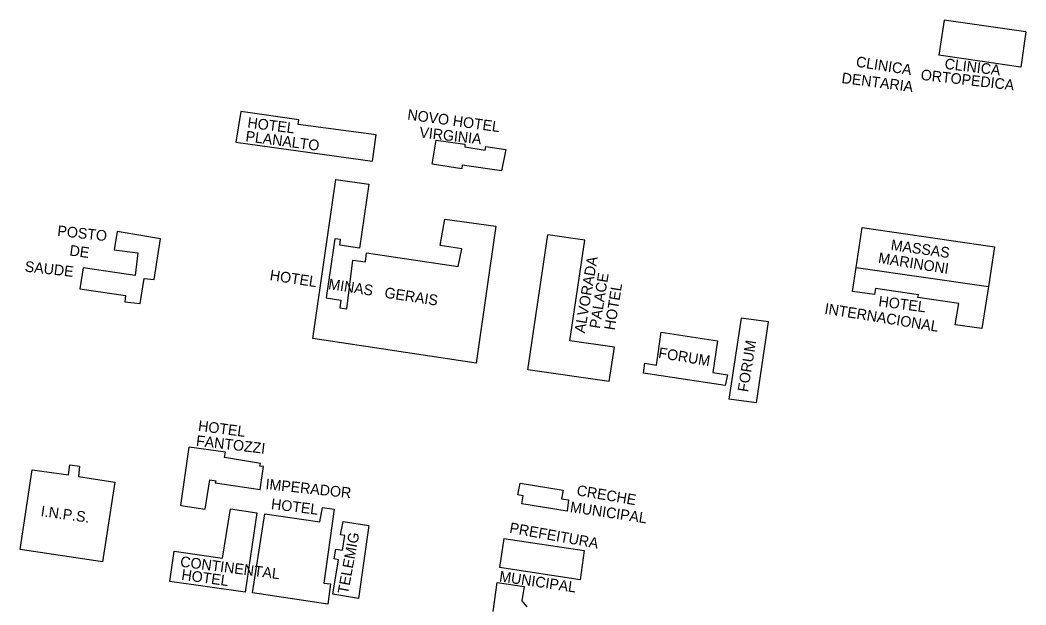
# Model space of a CAD drawing. Extents: x 325899 to 363134, y 7578590 to 7592502.
# Drawn here: x 337903.7 to 338282.4, y 7590177.9 to 7590398 of the extents above; entities that cross this region are included whole.
import ezdxf

# ---------------------------------------------------------------- set-up
doc = ezdxf.new("R2010")
doc.units = 0
doc.layers.add('EDIFEXISTENT', color=7, linetype='Continuous')
doc.layers.add('EDIFIDENTIF', color=7, linetype='Continuous')

msp = doc.modelspace()

# ---------------------------------------------------------------- linework, layer by layer
at = {"layer": 'EDIFEXISTENT'}
for p, q in [((338251.55, 7590398.05), (338249.66, 7590384.84)), ((338282.38, 7590393.63), (338251.55, 7590398.05)), ((338282.38, 7590393.63), (338280.49, 7590380.32)), ((338280.49, 7590380.32), (338249.66, 7590384.84)), ((338249.66, 7590384.84), (338249.66, 7590384.84)), ((337986.75, 7590363.66), (337984.97, 7590352.14)), ((338008.58, 7590360.47), (337986.75, 7590363.66)), ((337986.75, 7590363.66), (337986.75, 7590363.66)), ((338008.4, 7590358.72), (338008.58, 7590360.47)), ((338037.71, 7590354.92), (338008.4, 7590358.72)), ((338036.33, 7590344.99), (338037.71, 7590354.92)), ((337984.97, 7590352.14), (338036.33, 7590344.99)), ((338058.88, 7590343.78), (338060.3, 7590352.86)), ((338060.3, 7590352.86), (338071.14, 7590351.41)), ((338071.14, 7590351.41), (338071.08, 7590350.31)), ((338071.08, 7590350.31), (338078.77, 7590349.13)), ((338078.77, 7590349.13), (338079, 7590350.43)), ((338079, 7590350.43), (338086.53, 7590349.29)), ((338086.53, 7590349.29), (338084.94, 7590341.32)), ((338069.99, 7590342.1), (338058.88, 7590343.78)), ((338070.19, 7590343.4), (338069.99, 7590342.1)), ((338084.94, 7590341.32), (338070.19, 7590343.4)), ((338013.89, 7590278.15), (338022.51, 7590338.11)), ((338022.51, 7590338.11), (338035.03, 7590336.24)), ((338035.03, 7590336.24), (338031.5, 7590312.27)), ((338061.81, 7590313.17), (338063.64, 7590323.12)), ((338063.64, 7590323.12), (338082.84, 7590320.46)), ((338082.84, 7590320.46), (338075.44, 7590268.92)), ((338218.53, 7590304.91), (338220.73, 7590319.98)), ((338220.73, 7590319.98), (338270.62, 7590312.77)), ((337940.18, 7590318.51), (337939.1, 7590311.56)), ((337956.49, 7590315.75), (337940.18, 7590318.51)), ((338022.24, 7590315.78), (338018.89, 7590293.51)), ((338024.34, 7590315.52), (338022.24, 7590315.78)), ((338094.82, 7590266.47), (338102.37, 7590317.27)), ((338116.29, 7590315.21), (338102.37, 7590317.27)), ((337954.15, 7590300.36), (337956.49, 7590315.75)), ((338024.08, 7590313.31), (338024.34, 7590315.52)), ((338031.5, 7590312.27), (338024.08, 7590313.31)), ((338069.99, 7590311.92), (338061.81, 7590313.17)), ((338110.66, 7590277.31), (338116.29, 7590315.21)), ((338270.62, 7590312.77), (338268.24, 7590297.79)), ((337939.1, 7590311.56), (337947.96, 7590310.46)), ((337947.96, 7590310.46), (337947.04, 7590301.95)), ((338033.72, 7590307.1), (338034.11, 7590310.43)), ((338034.11, 7590310.43), (338068.67, 7590305.35)), ((338068.67, 7590305.35), (338069.99, 7590311.92)), ((337927.49, 7590304.78), (337926.2, 7590296.91)), ((337947.04, 7590301.95), (337927.49, 7590304.78)), ((338026.73, 7590289.32), (338028.94, 7590307.68)), ((338028.94, 7590307.68), (338033.72, 7590307.1)), ((338217.04, 7590295.9), (338218.53, 7590304.91)), ((338218.53, 7590304.91), (338268.24, 7590297.79)), ((337948.89, 7590291.33), (337950.37, 7590300.75)), ((337950.37, 7590300.75), (337954.15, 7590300.36)), ((337926.2, 7590296.91), (337943.39, 7590294.37)), ((338225.77, 7590297), (338225.38, 7590294.81)), ((338241.95, 7590294.67), (338225.77, 7590297)), ((338268.24, 7590297.79), (338265.73, 7590281.98)), ((337943.39, 7590294.37), (337943.1, 7590292.03)), ((338018.89, 7590293.51), (338024.4, 7590292.6)), ((338225.38, 7590294.81), (338217.04, 7590295.9)), ((338241.72, 7590293.63), (338241.95, 7590294.67)), ((338257.1, 7590291.38), (338241.72, 7590293.63)), ((337943.1, 7590292.03), (337948.89, 7590291.33)), ((338024.4, 7590292.6), (338024.11, 7590289.81)), ((338024.11, 7590289.81), (338026.73, 7590289.32)), ((338255.78, 7590283.34), (338257.1, 7590291.38)), ((338175.24, 7590285.89), (338170.49, 7590255.4)), ((338185.44, 7590284.47), (338175.24, 7590285.89)), ((338180.94, 7590254.03), (338185.44, 7590284.47)), ((338265.73, 7590281.98), (338255.78, 7590283.34)), ((338075.44, 7590268.92), (338013.89, 7590278.15)), ((338143.32, 7590268.21), (338145.08, 7590280.57)), ((338145.08, 7590280.57), (338166.26, 7590277.39)), ((338127.48, 7590274.96), (338110.66, 7590277.31)), ((338125.53, 7590262.02), (338127.48, 7590274.96)), ((338166.26, 7590277.39), (338164.53, 7590265.39)), ((338138.36, 7590265.11), (338138.96, 7590268.86)), ((338138.96, 7590268.86), (338143.32, 7590268.21)), ((338125.53, 7590262.02), (338094.82, 7590266.47)), ((338169.21, 7590260.56), (338138.36, 7590265.11)), ((338164.53, 7590265.39), (338169.98, 7590264.59)), ((338169.98, 7590264.59), (338169.21, 7590260.56)), ((338180.94, 7590254.03), (338170.49, 7590255.4)), ((337964.16, 7590215.31), (337967.37, 7590237.32)), ((337981.04, 7590235.46), (337967.37, 7590237.32)), ((337980.61, 7590233.36), (337981.04, 7590235.46)), ((337994.15, 7590231.14), (337980.61, 7590233.36)), ((337903.7, 7590198.75), (337908.27, 7590228.81)), ((337908.27, 7590228.81), (337921.89, 7590226.92)), ((337921.89, 7590226.92), (337922.46, 7590230.62)), ((337922.46, 7590230.62), (337926.01, 7590230.16)), ((337926.01, 7590230.16), (337925.72, 7590226.25)), ((337993.92, 7590230.1), (337994.15, 7590231.14)), ((337995.39, 7590229.97), (337993.92, 7590230.1)), ((337994.1, 7590221.39), (337995.39, 7590229.97)), ((337925.72, 7590226.25), (337939.37, 7590224.11)), ((337973.32, 7590213.96), (337975.15, 7590225.07)), ((337975.15, 7590225.07), (337977.41, 7590224.69)), ((337939.37, 7590224.11), (337934.72, 7590194.15)), ((337977.41, 7590224.69), (337977.18, 7590223.88)), ((337977.18, 7590223.88), (337994.1, 7590221.39)), ((338091.11, 7590219.38), (338091.99, 7590223.74)), ((338091.99, 7590223.74), (338108.12, 7590221.16)), ((338108.12, 7590221.16), (338107.55, 7590217.89)), ((338093.14, 7590219.04), (338091.11, 7590219.38)), ((338092.6, 7590216.02), (338093.14, 7590219.04)), ((338107.55, 7590217.89), (338110.22, 7590217.42)), ((338110.22, 7590217.42), (338109.67, 7590213.26)), ((337964.16, 7590215.31), (337973.32, 7590213.96)), ((337979.9, 7590195.55), (337982.92, 7590214.12)), ((337982.92, 7590214.12), (337992.82, 7590212.62)), ((338016.59, 7590209.15), (338017.59, 7590214.63)), ((338017.59, 7590214.63), (338021.93, 7590213.96)), ((338021.93, 7590213.96), (338018.1, 7590186.13)), ((338109.67, 7590213.26), (338092.6, 7590216.02)), ((337992.82, 7590212.62), (337988.37, 7590182.71)), ((337991.21, 7590182.47), (337995.81, 7590212.18)), ((337995.81, 7590212.18), (338016.59, 7590209.15)), ((338024.33, 7590204.28), (338025.28, 7590209.28)), ((338025.28, 7590209.28), (338035.02, 7590207.86)), ((338035.02, 7590207.86), (338031.09, 7590180.36)), ((338025.98, 7590204.08), (338024.33, 7590204.28)), ((338025.1, 7590198.49), (338025.98, 7590204.08)), ((338085.81, 7590202.92), (338084.17, 7590192.06)), ((338085.81, 7590202.92), (338116.07, 7590198.43)), ((337934.72, 7590194.15), (337903.7, 7590198.75)), ((338021.89, 7590195.23), (338022.54, 7590198.93)), ((338022.54, 7590198.93), (338025.1, 7590198.49)), ((338116.07, 7590198.43), (338114.57, 7590187.32)), ((337960.01, 7590186.71), (337961.69, 7590198.21)), ((337961.69, 7590198.21), (337979.9, 7590195.55)), ((338021.5, 7590181.98), (338023.54, 7590194.95)), ((338023.54, 7590194.95), (338021.89, 7590195.23)), ((338114.57, 7590187.32), (338084.17, 7590192.06)), ((337988.37, 7590182.71), (337960.01, 7590186.71)), ((338018.1, 7590186.13), (338020.56, 7590185.82)), ((338020.56, 7590185.82), (338019.5, 7590178.15)), ((338081.78, 7590175.41), (338083.28, 7590186.34)), ((338083.28, 7590186.34), (338093.45, 7590184.89)), ((338093.45, 7590184.89), (338092.63, 7590179.41)), ((338019.5, 7590178.15), (337991.21, 7590182.47)), ((338031.09, 7590180.36), (338021.5, 7590181.98)), ((338092.63, 7590179.41), (338094.5, 7590177.2))]:
    msp.add_line(p, q, dxfattribs=at)

# ---------------------------------------------------------------- texts
at = {"layer": 'EDIFIDENTIF'}
for s, rotation, p in [('CLINICA', 351.2238, (338218.21, 7590380.54)), ('CLINICA', 352.9951, (338251.6, 7590379.74)), ('DENTARIA', 352.7691, (338212.83, 7590374.39)), ('ORTOPEDICA', 353.4768, (338242.62, 7590375.59)), ('HOTEL', 352.8424, (337989.12, 7590357.59)), ('NOVO HOTEL', 352.1661, (338049.33, 7590360.63)), ('VIRGINIA', 353.4385, (338053.86, 7590353.94)), ('PLANALTO', 352.534, (337988.39, 7590352.45)), ('POSTO', 353.8537, (337917.57, 7590316.84)), ('DE', 352.3278, (337922.11, 7590309.48)), ('MASSAS', 352.1024, (338231.33, 7590311.53)), ('ALVORADA', 80.33, (338116.29, 7590280.04)), ('MARINONI', 351.0084, (338226.57, 7590306.68)), ('SAUDE', 353.5394, (337905.3, 7590303.43)), ('HOTEL   MINAS   GERAIS', 351.3115, (337997.51, 7590300.2)), ('PALACE', 80.8491, (338121.97, 7590281.73)), ('HOTEL', 80.7898, (338127.53, 7590281.13)), ('HOTEL', 352.5428, (338226.7, 7590290.35)), ('INTERNACIONAL', 350.8414, (338206.38, 7590287.6)), ('FORUM', 350.6252, (338143.8, 7590270.97)), ('FORUM', 80.8156, (338177.74, 7590257.87)), ('HOTEL', 352.4788, (337970.54, 7590243.48)), ('FANTOZZI', 353.3521, (337969.78, 7590237.84)), ('IMPERADOR', 353.9198, (337995.95, 7590221.51)), ('CRECHE', 350.4108, (338113.04, 7590219.2)), ('HOTEL', 352.9083, (337998.01, 7590214.04)), ('I.N.P.S.', 352.1571, (337911.29, 7590211.36)), ('MUNICIPAL', 351.4943, (338110.56, 7590212.91)), ('PREFEITURA', 349.8014, (338087.72, 7590205.1)), ('TELEMIG', 79.3615, (338027.12, 7590181.79)), ('CONTINENTAL', 352.7264, (337963.8, 7590192.35)), ('HOTEL', 352.0945, (337964.25, 7590187.43)), ('MUNICIPAL', 351.6841, (338083.91, 7590186.78))]:
    msp.add_text(s, height=4, rotation=rotation, dxfattribs=at).set_placement(p)

doc.saveas('drawing.dxf')
